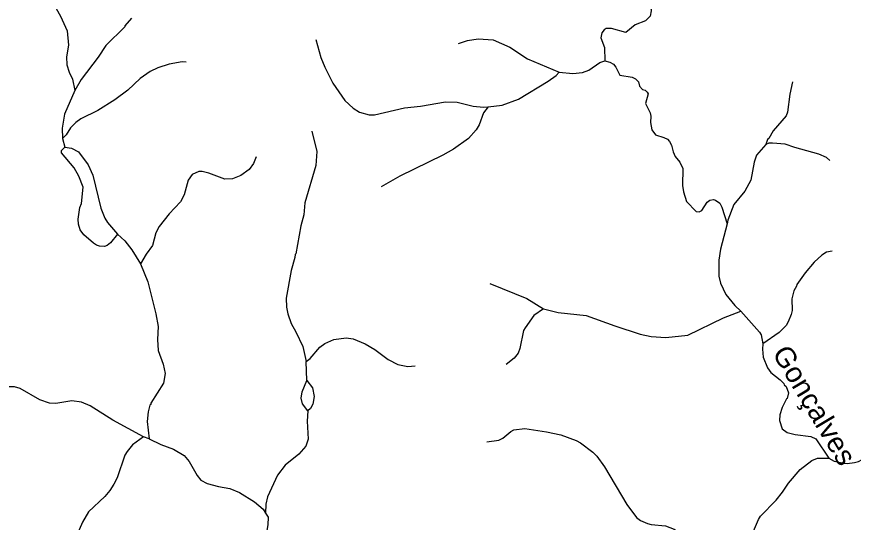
# Model space of a CAD drawing. Extents: x 346.5 to 372.4, y 7400.3 to 7428.2.
# Drawn here: x 356.096 to 359.423, y 7414.626 to 7416.636 of the extents above; entities that cross this region are included whole.
import ezdxf
from ezdxf.enums import TextEntityAlignment as Align

# ---------------------------------------------------------------- set-up
doc = ezdxf.new("R2010")
doc.units = 0
doc.header["$LTSCALE"] = 0.032
doc.layers.add('2', color=7, linetype='Continuous', lineweight=25)
doc.layers.add('7', color=7, linetype='Continuous', lineweight=25)
doc.layers.add('61', color=7, linetype='Continuous')

msp = doc.modelspace()

# ---------------------------------------------------------------- linework, layer by layer
at = {"layer": '2'}
for points in [[(356.2877, 7416.1178), (356.3138, 7416.1134), (356.3417, 7416.099), (356.3803, 7416.0481), (356.3991, 7416.0059), (356.4312, 7415.8755), (356.447, 7415.835), (356.4572, 7415.8186), (356.4977, 7415.7718), (356.4692, 7415.7379), (356.4562, 7415.7269), (356.4451, 7415.7232), (356.426, 7415.724), (356.4133, 7415.7274), (356.4016, 7415.7357), (356.3638, 7415.7696), (356.3493, 7415.7889), (356.3423, 7415.811), (356.3405, 7415.8313), (356.348, 7415.8772), (356.3544, 7415.8933), (356.3612, 7415.9586), (356.3436, 7416.0018), (356.3245, 7416.0352), (356.2751, 7416.0956), (356.275, 7416.1045)], [(357.2495, 7415.1903), (357.2725, 7415.1601), (357.2787, 7415.1261), (357.2737, 7415.0952), (357.2652, 7415.0791), (357.2534, 7415.0687), (357.2322, 7415.0966), (357.2277, 7415.1202), (357.2317, 7415.145)]]:
    msp.add_lwpolyline(points, close=True, dxfattribs=at)
at = {"layer": '7'}
for p, q in [((357.2495, 7415.1903), (357.2477, 7415.2649)), ((356.6234, 7414.9578), (356.6008, 7414.9655))]:
    msp.add_line(p, q, dxfattribs=at)
for points in [[(356.2158, 7416.8684), (356.2063, 7416.8245), (356.2103, 7416.7798), (356.2231, 7416.732), (356.2358, 7416.7002), (356.2709, 7416.638), (356.2964, 7416.5806), (356.302, 7416.5232), (356.2948, 7416.477), (356.2956, 7416.4451), (356.3044, 7416.4164), (356.3187, 7416.3877), (356.3279, 7416.3426)], [(358.6008, 7416.6897), (358.6195, 7416.6659), (358.6195, 7416.6603), (358.6155, 7416.6388), (358.5972, 7416.6196), (358.555, 7416.6037), (358.5191, 7416.5742), (358.4609, 7416.5894), (358.4482, 7416.5902), (358.4402, 7416.5894), (358.433, 7416.5846), (358.4226, 7416.5726), (358.4195, 7416.5519), (358.4338, 7416.5137), (358.4353, 7416.4609)], [(356.5522, 7416.6308), (356.5267, 7416.6005), (356.5259, 7416.5957), (356.4502, 7416.5224), (356.4207, 7416.4754), (356.353, 7416.3869), (356.3279, 7416.3426)], [(357.2854, 7416.5463), (357.3061, 7416.4738), (357.3213, 7416.4356), (357.3531, 7416.3718), (357.401, 7416.3033), (357.4337, 7416.273), (357.46, 7416.257), (357.4982, 7416.2467), (357.5197, 7416.2459), (357.6385, 7416.2738), (357.7022, 7416.2801), (357.801, 7416.2985), (357.8473, 7416.2961), (357.911, 7416.2809), (357.9526, 7416.2763), (357.9712, 7416.2777)], [(357.8528, 7416.5296), (357.8887, 7416.5423), (357.9317, 7416.5487), (357.9907, 7416.5439), (358.0577, 7416.516), (358.127, 7416.469), (358.2535, 7416.4164)], [(356.7706, 7416.4563), (356.7539, 7416.4571), (356.7029, 7416.4483), (356.6582, 7416.4332), (356.6271, 7416.418), (356.5873, 7416.3909), (356.5379, 7416.3447), (356.4861, 7416.3064), (356.4191, 7416.2634), (356.3514, 7416.2299), (356.3315, 7416.2164), (356.31, 7416.1941), (356.2929, 7416.1672), (356.2781, 7416.1522)], [(358.2535, 7416.4164), (358.3079, 7416.4101), (358.3462, 7416.414), (358.3717, 7416.4236), (358.4147, 7416.4539), (358.4353, 7416.4609)], [(358.4353, 7416.4609), (358.4555, 7416.4552), (358.4693, 7416.4476), (358.4792, 7416.4364), (358.4952, 7416.4045), (358.5438, 7416.3965), (358.5565, 7416.3893), (358.5693, 7416.3774), (358.5733, 7416.3599), (358.5852, 7416.3471), (358.5948, 7416.3447), (358.6036, 7416.3359), (358.6067, 7416.3304), (358.5972, 7416.2913), (358.6155, 7416.2539), (358.6179, 7416.2411), (358.6163, 7416.2156), (358.6219, 7416.1861), (358.637, 7416.167), (358.6697, 7416.1566), (358.684, 7416.1495), (358.6928, 7416.1399), (358.7, 7416.1263), (358.7064, 7416.0993), (358.7143, 7416.0801), (358.7335, 7416.0578), (358.7454, 7416.0331), (358.7438, 7415.9654), (358.7478, 7415.9399), (358.7597, 7415.9016), (358.798, 7415.8625), (358.81, 7415.8609), (358.8211, 7415.8657), (358.8426, 7415.8984), (358.853, 7415.9072), (358.8666, 7415.9096), (358.8753, 7415.9064), (358.8928, 7415.8944), (358.9008, 7415.8785), (358.9213, 7415.8128)], [(357.9712, 7416.2777), (358.0274, 7416.2849), (358.0911, 7416.308), (358.2091, 7416.3798), (358.241, 7416.4021), (358.2535, 7416.4164)], [(359.1814, 7416.3774), (359.1702, 7416.3288), (359.1614, 7416.257), (359.1558, 7416.2427), (359.1048, 7416.1821), (359.0873, 7416.1518), (359.0823, 7416.1488), (359.0747, 7416.1282)], [(356.3279, 7416.3426), (356.2868, 7416.2491), (356.2765, 7416.1933), (356.2781, 7416.1522), (356.2877, 7416.1178)], [(357.9712, 7416.2777), (357.9532, 7416.2546), (357.9349, 7416.206), (357.9238, 7416.1861), (357.8935, 7416.1518), (357.8337, 7416.1104), (357.7915, 7416.0857), (357.6193, 7416.0028), (357.5452, 7415.9598)], [(357.2695, 7416.1813), (357.2894, 7416.1008), (357.2862, 7416.0451), (357.2416, 7415.8968), (357.2376, 7415.849), (357.2256, 7415.8044), (357.2065, 7415.6936), (357.2033, 7415.6904), (357.2025, 7415.6785), (357.1874, 7415.6275), (357.1683, 7415.5175), (357.1691, 7415.4808), (357.1746, 7415.4553), (357.1874, 7415.4171), (357.2065, 7415.3836), (357.2336, 7415.3246), (357.2477, 7415.2649)], [(359.0747, 7416.1282), (359.0379, 7416.0865), (359.0283, 7416.0578), (359.0156, 7415.9861), (358.9917, 7415.9431), (358.9486, 7415.8896), (358.924, 7415.8274), (358.9213, 7415.8128)], [(359.3304, 7416.065), (359.3168, 7416.0761), (359.2865, 7416.0905), (359.1909, 7416.116), (359.1527, 7416.1295), (359.1017, 7416.1335), (359.0875, 7416.1332), (359.0747, 7416.1282)], [(357.0487, 7416.0793), (357.0376, 7416.053), (357.0208, 7416.0291), (356.9882, 7416.0044), (356.9547, 7415.9916), (356.9244, 7415.9909), (356.8606, 7416.0148), (356.8336, 7416.0211), (356.8208, 7416.0211), (356.7945, 7416.0084), (356.7777, 7415.9869), (356.7618, 7415.9287), (356.7475, 7415.9008), (356.702, 7415.853), (356.663, 7415.8028), (356.6502, 7415.7773), (356.6359, 7415.7263), (356.6112, 7415.6928), (356.5882, 7415.6536)], [(358.9213, 7415.8128), (358.8944, 7415.7119), (358.8881, 7415.6689), (358.8881, 7415.6051), (358.8944, 7415.5765), (358.9167, 7415.5318), (358.9526, 7415.488), (358.9757, 7415.4658)], [(356.4977, 7415.7718), (356.5259, 7415.7454), (356.5538, 7415.7088), (356.5882, 7415.6536)], [(359.3387, 7415.7037), (359.3171, 7415.6999), (359.2977, 7415.6888), (359.2674, 7415.6609), (359.2323, 7415.6179), (359.1981, 7415.5717), (359.1973, 7415.5645), (359.1861, 7415.5462), (359.1789, 7415.5143), (359.1797, 7415.4681), (359.1766, 7415.4521), (359.1646, 7415.4234), (359.1558, 7415.4091), (359.1288, 7415.3804), (359.0629, 7415.3356)], [(356.5882, 7415.6536), (356.6184, 7415.5828), (356.6502, 7415.4553), (356.659, 7415.4043), (356.6566, 7415.3533), (356.659, 7415.3095), (356.6781, 7415.2545), (356.6869, 7415.2178), (356.6797, 7415.1796), (356.6303, 7415.0999), (356.6295, 7415.0943), (356.6255, 7415.0919), (356.6192, 7415.0648), (356.6152, 7415.0266), (356.6234, 7414.9578)], [(357.9772, 7415.5757), (358.1246, 7415.5159), (358.1907, 7415.4752)], [(358.1907, 7415.4752), (358.1525, 7415.4481), (358.1182, 7415.3995), (358.111, 7415.3884), (358.0975, 7415.3167), (358.0903, 7415.2983), (358.0744, 7415.2784), (358.0425, 7415.2537)], [(358.1907, 7415.4752), (358.2489, 7415.4601), (358.3605, 7415.4489), (358.4753, 7415.4067), (358.5757, 7415.374), (358.6187, 7415.3653), (358.6777, 7415.3605), (358.7653, 7415.37), (358.9072, 7415.4394), (358.9757, 7415.4658)], [(358.9757, 7415.4658), (359.0506, 7415.382), (359.057, 7415.3716), (359.0629, 7415.3356)], [(357.2477, 7415.2649), (357.2639, 7415.2768), (357.3021, 7415.3222), (357.3213, 7415.3374), (357.3579, 7415.3533), (357.4058, 7415.3597), (357.4345, 7415.3549), (357.4823, 7415.3358), (357.5205, 7415.3134), (357.5739, 7415.2736), (357.6113, 7415.2529), (357.6512, 7415.2449), (357.6807, 7415.2481)], [(359.0629, 7415.3356), (359.0615, 7415.3149), (359.065, 7415.2832), (359.0817, 7415.2401), (359.0945, 7415.2218), (359.1327, 7415.1931), (359.1463, 7415.178), (359.1479, 7415.1724), (359.1558, 7415.166), (359.1654, 7415.1413), (359.1606, 7415.1182), (359.1574, 7415.1166), (359.1407, 7415.0824), (359.1303, 7415.0537), (359.1295, 7415.0313), (359.1407, 7414.9979), (359.1606, 7414.9827), (359.1925, 7414.9755), (359.2547, 7414.9676), (359.2746, 7414.9572), (359.3257, 7414.8812)], [(359.3257, 7414.8812), (359.3464, 7414.8694), (359.3838, 7414.8608), (359.3981, 7414.8592), (359.4284, 7414.8632), (359.4443, 7414.8672), (359.4579, 7414.8759), (359.4913, 7414.915), (359.5065, 7414.9437), (359.5137, 7414.9724), (359.5145, 7415.0011), (359.5113, 7415.0369), (359.5145, 7415.0401), (359.5176, 7415.056), (359.5288, 7415.076), (359.5464, 7415.0991), (359.591, 7415.1285), (359.6834, 7415.1867), (359.7121, 7415.1915), (359.7907, 7415.1864), (359.8079, 7415.1905)], [(356.6008, 7414.9655), (356.4781, 7415.0321), (356.3889, 7415.0887), (356.3538, 7415.1039), (356.3155, 7415.1094), (356.2518, 7415.0983), (356.2263, 7415.0999), (356.188, 7415.1126), (356.1099, 7415.158), (356.0876, 7415.1644), (356.051, 7415.1652), (355.9999, 7415.1573), (355.9489, 7415.1421), (355.8629, 7415.1023), (355.8246, 7415.0895), (355.713, 7415.0776), (355.678, 7415.0664), (355.6405, 7415.0417), (355.6198, 7415.0202), (355.5648, 7414.9341), (355.5258, 7414.899), (355.4995, 7414.8799)], [(357.2534, 7415.0687), (357.2511, 7415.0282), (357.2559, 7414.9564), (357.2463, 7414.9285), (357.2177, 7414.8974), (357.1643, 7414.8536), (357.1332, 7414.813), (357.0933, 7414.7269), (357.087, 7414.6982), (357.086, 7414.6629)], [(357.966, 7414.9453), (358.013, 7414.9532), (358.029, 7414.9604), (358.0616, 7414.9875), (358.0736, 7414.9939), (358.1166, 7414.9995), (358.2027, 7414.9859), (358.2601, 7414.9732), (358.3207, 7414.9516), (358.3382, 7414.9421), (358.3868, 7414.9054), (358.4027, 7414.8895), (358.4338, 7414.8465), (358.5223, 7414.6966), (358.5613, 7414.6456), (358.5773, 7414.6329), (358.6044, 7414.6209), (358.6187, 7414.6169), (358.6761, 7414.6113), (358.7104, 7414.5986), (358.743, 7414.5771), (358.8069, 7414.5119)], [(356.6008, 7414.9655), (356.5562, 7414.9341), (356.5355, 7414.9078), (356.5267, 7414.8935), (356.4956, 7414.8034), (356.4829, 7414.7779), (356.4669, 7414.7524), (356.4462, 7414.7285), (356.3817, 7414.6671), (356.3586, 7414.6265), (356.3275, 7414.5564), (356.3068, 7414.5245), (356.2725, 7414.4926), (356.2119, 7414.4623), (356.1729, 7414.4201)], [(356.6234, 7414.9578), (356.6694, 7414.9357), (356.7204, 7414.9166), (356.7618, 7414.8911), (356.7817, 7414.8672), (356.8144, 7414.8114), (356.8288, 7414.7931), (356.8543, 7414.7803), (356.8989, 7414.7683), (356.9435, 7414.7604), (356.9818, 7414.7444), (357.0423, 7414.7078), (357.0759, 7414.6775), (357.086, 7414.6629)], [(358.9026, 7414.5094), (358.9227, 7414.5104), (358.9678, 7414.5229), (358.9837, 7414.5316), (359.0012, 7414.5468), (359.0219, 7414.5819), (359.0459, 7414.6377), (359.0546, 7414.6504), (359.1168, 7414.7142), (359.1415, 7414.746), (359.1654, 7414.7819), (359.2116, 7414.8353), (359.2579, 7414.8711), (359.2802, 7414.8807), (359.3257, 7414.8812)], [(357.086, 7414.6629), (357.0965, 7414.6458), (357.0949, 7414.6153), (357.0902, 7414.5851), (357.0686, 7414.499), (357.0678, 7414.4846), (357.0737, 7414.4603)]]:
    msp.add_lwpolyline(points, dxfattribs=at)

# ---------------------------------------------------------------- texts
at = {"layer": '61', "width": 1.05}
msp.add_text('Gonçalves', height=0.08, rotation=300.883, dxfattribs=at).set_placement((359.2347, 7415.0712), align=Align.CENTER)

doc.saveas('drawing.dxf')
